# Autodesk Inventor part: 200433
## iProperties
Created: 2007-12
Part Number: 200433
Document SubType Name: Modeling
Designer: MM
Density: 7.85 g/cm^3
Mass: 44.1035 g
Surface Area: 50.9461 cm^2
Volume: 5.61828 cm^3
Material: Steel
Description: CORNER BRACKET
Component Category: Lower Component
Author: MM
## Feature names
1. TaggingFeature2
